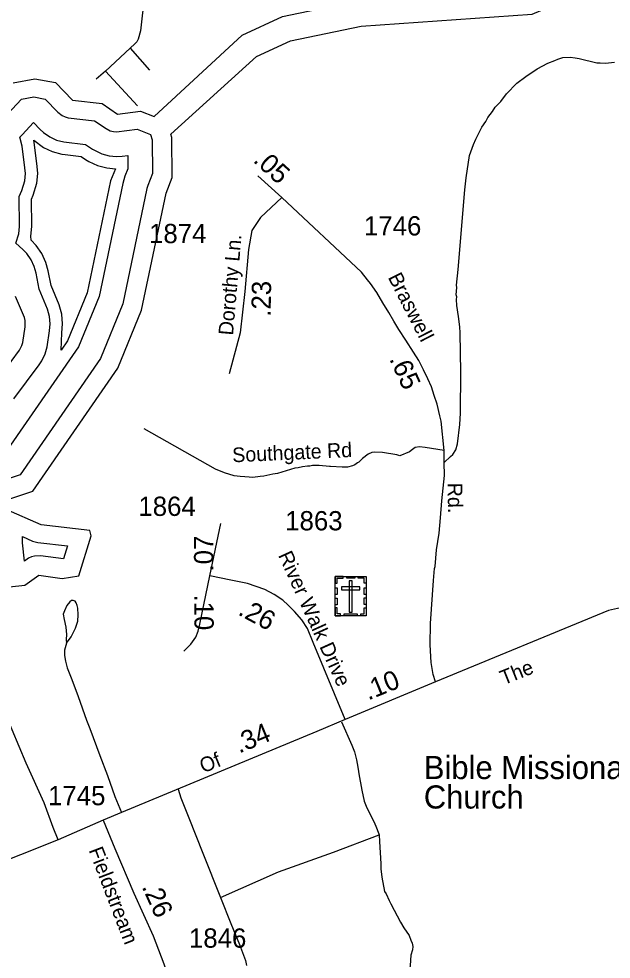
# Model space of a CAD drawing. Extents: x 2220236 to 2384410, y 720751 to 894131.
# Drawn here: x 2329286 to 2333123, y 778623 to 784717 of the extents above; entities that cross this region are included whole.
import ezdxf

# ---------------------------------------------------------------- set-up
doc = ezdxf.new("R2010")
doc.units = 0
doc.layers.add('Default', color=7, linetype='Continuous')

msp = doc.modelspace()

# ---------------------------------------------------------------- linework, layer by layer
at = {"layer": 'Default'}
for p, q in [((2330007.3, 784526.8), (2329846.9, 784377)), ((2330007.3, 784526.8), (2330132.6, 784384.6)), ((2329846.9, 784377), (2329787.7, 784325.1)), ((2329846.9, 784377), (2330054.7, 784153.8)), ((2330990.5, 783558.1), (2330834.7, 783699.1))]:
    msp.add_line(p, q, dxfattribs=at)
for points in [[(2330163, 784084.9), (2330733.1, 784610.8), (2330993, 784731.7), (2331481.8, 784832.8), (2332572.7, 784909.9), (2332829.5, 785019), (2332935.7, 785114), (2333181.2, 785476.6)], [(2330270, 783969.1), (2330825, 784472.6), (2331044.9, 784574.9), (2331504.3, 784670), (2332611.6, 784748.2), (2332918.7, 784878.6), (2333058.6, 785003.8), (2333331.5, 785385.3)], [(2330143.3, 785190.9), (2330086.7, 784756), (2330074.5, 784639.9), (2330058.8, 784585.8), (2330050.1, 784568), (2330037.9, 784554.3), (2330007.3, 784526.8)], [(2332041.4, 781841.1), (2332082.8, 781881), (2332096.7, 781893.2), (2332116.5, 781923.2), (2332128, 781963.5), (2332142.6, 782087.5), (2332147.8, 782161.6), (2332148.9, 782427.5), (2332144.4, 782681.2), (2332141.9, 782721.3), (2332135, 782787), (2332124.3, 782859), (2332121.9, 782898.9), (2332123.8, 782915), (2332119.6, 782928.9), (2332123.1, 782976.8), (2332120.9, 782990.9), (2332131.7, 783093), (2332174.3, 783609.1), (2332183.5, 783687.3), (2332205.8, 783831.5), (2332231.2, 783901.7), (2332246.7, 783937.8), (2332285.8, 784014.2), (2332311.5, 784050.5), (2332323.3, 784076.6), (2332354.8, 784116.9), (2332372.5, 784145), (2332408, 784181.4), (2332445.4, 784231.8), (2332512.8, 784300.6), (2332570.3, 784343.1), (2332643.6, 784393.9), (2332713.1, 784430.6), (2332759.1, 784447.1), (2332776.9, 784455.2), (2332810.7, 784465.6), (2332856.7, 784468.1), (2332888.8, 784464.6), (2332914.8, 784460.8), (2333031, 784432), (2333051, 784432.2), (2333087.1, 784428.7), (2333144.9, 784435.2)], [(2329248.9, 784302.1), (2329390, 784327.5), (2329524.1, 784303.4), (2329633, 784189.7), (2329824.9, 784168), (2329926, 784100), (2330075.1, 784119.1), (2330163, 784084.9)], [(2329179.2, 784064.9), (2329302.5, 784195.9), (2329383.1, 784210.4), (2329457.3, 784197), (2329539.5, 784111.5), (2329566, 784090.6), (2329585, 784081.8), (2329605.3, 784076.4), (2329775.3, 784056.9), (2329852, 784005.3), (2329878.1, 783992), (2329898.4, 783986.6), (2329919.1, 783984.8), (2330053.2, 784001.1), (2330139.1, 783967.6), (2330150.4, 783932.4), (2330152.8, 783715), (2330121.7, 783637), (2330115.5, 783617.1), (2329958.8, 782869.7), (2329813.9, 782514.7), (2329294.3, 781761.7), (2329150.5, 781714.3)], [(2329253.5, 782253.6), (2329417.5, 782473.7), (2329435.5, 782501), (2329456.1, 782545.2), (2329468.8, 782592.3), (2329485.6, 782695.4), (2329489.1, 782740), (2329484.8, 782788.7), (2329472, 782835.8), (2329418.3, 782964.2), (2329397.8, 783069), (2329386.1, 783111.2), (2329365.6, 783155.5), (2329337.5, 783195.5), (2329311.5, 783222.4), (2329267.4, 783262.8), (2329285.9, 783323.3), (2329290, 783371.9), (2329288.5, 783565), (2329305.5, 783604.7), (2329323.8, 783666.2), (2329328.1, 783714.8), (2329325.8, 783750.4), (2329307.8, 783890.8), (2329293, 783950.9), (2329306.8, 783965.9), (2329381, 784045.8), (2329424.1, 784000.8), (2329446, 783980), (2329486, 783952), (2329530.3, 783931.4), (2329577.6, 783918.8), (2329718.5, 783902.3), (2329762.6, 783872.6), (2329823.3, 783841.7), (2329870.7, 783829.1), (2329919.1, 783824.8), (2329954.7, 783827.1), (2329991.6, 783831.8), (2329992.5, 783744.8), (2329973, 783696.5), (2329959, 783650), (2329805.3, 782916.7)], [(2329195, 781595.5), (2329377.1, 781655.5), (2329927.1, 782452.4), (2330081.1, 782829.6), (2330240, 783587.6), (2330280, 783687.7), (2330277.1, 783946.9), (2330270, 783969.1)], [(2329560.2, 782569.7), (2329564.5, 782682.7), (2329569, 782740), (2329563.5, 782802.5), (2329547.3, 782863.2), (2329495.2, 782987.7), (2329476.4, 783084.4), (2329461.4, 783138.6), (2329434.7, 783195.5), (2329398.8, 783246.9), (2329365.6, 783281.5), (2329364.6, 783309.4), (2329370.1, 783371.9), (2329368.5, 783548.9), (2329379.2, 783573.3), (2329402.5, 783652.3), (2329408.1, 783714.8), (2329405, 783760.6), (2329387.2, 783901), (2329382.2, 783930.3), (2329446, 783882.8), (2329502.8, 783856.2), (2329563.5, 783840), (2329585.6, 783836.8), (2329690, 783825.1), (2329717.9, 783806.3), (2329739, 783793), (2329795.8, 783766.5), (2329856.5, 783750.3), (2329912.3, 783745.4), (2329880.7, 783666.4), (2329728.4, 782940.3), (2329601.6, 782629.6), (2329560.2, 782569.7)], [(2330990.5, 783558.1), (2330851.9, 783429.3), (2330795.5, 783344.7), (2330772.6, 783221.2), (2330749.8, 782950.4), (2330720.4, 782682.8), (2330648.6, 782415.3)], [(2331985, 780419.4), (2331970.5, 780467.4), (2331957.2, 780546.3), (2331950, 780660), (2331953.3, 780798.6), (2331971.6, 781076), (2331978.8, 781154.1), (2331982.7, 781168.1), (2331991.5, 781276.3), (2332008.2, 781384.4), (2332017.3, 781482.4), (2332025.9, 781592.2), (2332042.3, 781756.5), (2332041.4, 781841.1), (2332042, 781919.1), (2332021.9, 782110.5), (2332013.3, 782145.1), (2331996, 782218.7), (2331976.5, 782275), (2331959.2, 782331.2), (2331935.4, 782383.2), (2331907.3, 782441.6), (2331877.1, 782502.2), (2331842.5, 782556.3), (2331792.7, 782634.2), (2331747.3, 782704.5), (2331714.9, 782758.6), (2331682.4, 782814.8), (2331643.5, 782875.4), (2331604.6, 782942.5), (2331564.8, 783002.1), (2331544.1, 783024.7), (2331506.6, 783075.6), (2330990.5, 783558.1)], [(2329125.3, 782349.2), (2329289.3, 782569.3), (2329305.7, 782599.9), (2329311.3, 782620.2), (2329327.5, 782720.9), (2329327.3, 782760.9), (2329321.7, 782781.1), (2329264.5, 782917.3)], [(2329805.3, 782916.7), (2329672.4, 782591.3), (2329193, 781896.8)], [(2332042, 781919.1), (2331918.4, 781939.1), (2331880.4, 781942.8), (2331854.4, 781938.5), (2331836.5, 781926.4), (2331816.7, 781910.2), (2331754.9, 781885.4), (2331734.9, 781891.2), (2331642.8, 781906.3), (2331592.9, 781909.6), (2331572.8, 781905.4), (2331549.1, 781895.2), (2331511.4, 781866.9), (2331487.5, 781844.5), (2331479.7, 781840.4), (2331461.8, 781826.2), (2331447.9, 781820.1), (2331414, 781811.7), (2331380, 781811.5), (2331305.9, 781814.7), (2331298, 781816.5), (2331231.9, 781821.8), (2331188, 781821.3), (2331171.9, 781817.2), (2331155.9, 781816.9), (2331124.1, 781812.6), (2331096.1, 781806.3), (2331074.2, 781804.2), (2330962.5, 781770.8), (2330930.7, 781766.5), (2330872.8, 781754), (2330848.8, 781749.8), (2330800.9, 781745.2), (2330778.9, 781746.9), (2330750.5, 781748.1), (2330720.2, 781750.3), (2330681.3, 781754.6), (2330618.6, 781774.1), (2330560.2, 781797.9), (2330097.4, 782059.7)], [(2329226, 781035.5), (2329325, 781046.1), (2329416.1, 781112.2), (2329567, 781088.8), (2329675, 781106.3), (2329755, 781365.7), (2329746, 781401.4), (2329430, 781437.7), (2329204, 781536.8)], [(2330522.3, 781106.7), (2330593.6, 781447)], [(2329322.8, 781202.1), (2329310.3, 781320.9), (2329309.2, 781361.7), (2329374.9, 781332.7), (2329409.3, 781323.4), (2329601, 781301.3), (2329575.4, 781217.8), (2329427.3, 781235.7), (2329388.4, 781235.3), (2329368.1, 781229.8), (2329349, 781221), (2329322.8, 781202.1)], [(2330355.8, 780619.4), (2330400.3, 780663.2), (2330432.1, 780710.5), (2330447.6, 780748.8), (2330458.2, 780793.7), (2330522.3, 781106.7)], [(2331400.6, 780175.5), (2331193.5, 780675.4), (2331155.6, 780765.9), (2331119.7, 780821.4), (2331072.4, 780875.2), (2331031.6, 780916), (2330995.7, 780948.7), (2330940.7, 780985.4), (2330878.7, 781018.8), (2330767.7, 781057.1), (2330658.4, 781080), (2330522.3, 781106.7)], [(2329540.3, 779395.6), (2329509, 779475.4), (2329450.4, 779635.2), (2329333.3, 779893.5), (2329149.7, 780325), (2329043.3, 780591.3), (2329000.7, 780707.1), (2328984.7, 780755), (2328984.7, 780789.7), (2328995.3, 780829.6), (2329022, 780869.6), (2329072.5, 780976.1)], [(2329595, 780671.6), (2329625.2, 780712.4), (2329653.6, 780767.5), (2329667.8, 780813.6), (2329669.6, 780854.5), (2329667.8, 780897.1), (2329664.2, 780914.8), (2329657.1, 780932.6), (2329651.8, 780943.2), (2329637.6, 780946.8), (2329627, 780946.8), (2329616.3, 780937.9), (2329596.8, 780914.8), (2329580.8, 780881.1), (2329573.8, 780858), (2329579.1, 780824.3), (2329589.7, 780774.6), (2329595, 780726.6), (2329593.3, 780694.7), (2329595, 780671.6)], [(2334401.3, 780175.6), (2334301.5, 780217.3), (2334191.6, 780259), (2334010.9, 780345), (2333880.8, 780438.5), (2333782.2, 780532.1), (2333683.7, 780608), (2333496, 780755.2), (2333435.4, 780802), (2333358.3, 780851.3), (2333307, 780886.5), (2333267.3, 780898.1), (2333233.2, 780900.6), (2333204.2, 780903.2), (2333163, 780895.2), (2333106.7, 780882.2), (2331985, 780419.4)], [(2329595, 780671.6), (2329582.6, 780625.4), (2329582.6, 780591.7), (2329587.9, 780554.4), (2329598.6, 780510), (2329628.8, 780435.5), (2329671.3, 780325.4), (2329724.6, 780170.9), (2329745.9, 780117.7), (2329809.7, 779943.5), (2329859.4, 779812.1), (2329907.3, 779677.2), (2329949.9, 779572.4)], [(2331985, 780419.4), (2331400.6, 780175.5)], [(2331400.6, 780175.5), (2331216.8, 780098.7), (2329949.9, 779572.4), (2329831.5, 779523.6)], [(2331375.6, 780160.2), (2331442.6, 780008.8), (2331460.2, 779965.6), (2331474.2, 779915.3), (2331478.4, 779891.4), (2331485, 779853.3), (2331489.2, 779823.5), (2331507.7, 779719), (2331523.7, 779647.3), (2331540.6, 779602.7), (2331585.9, 779515.7), (2331598.3, 779484.3), (2331618.9, 779435.2), (2331621.1, 779429)], [(2330317.1, 779724.8), (2330336.1, 779667.9), (2330387.8, 779538.6), (2330477.3, 779309.4), (2330592.8, 779021.5)], [(2329831.5, 779523.6), (2329540.3, 779395.6), (2329050.9, 779201.8), (2328716.7, 779064), (2328692.8, 779055.7), (2328614.3, 779022.5), (2328493.8, 778971.5), (2328306, 778890.9), (2328185.4, 778832.3), (2328098.2, 778796.3)], [(2329831.5, 779523.6), (2329908.2, 779341), (2330030.6, 779050.7), (2330155.7, 778773.7), (2330224.9, 778592.6), (2330278.1, 778435.5), (2330320.7, 778321), (2330342, 778241.1)], [(2330592.8, 779021.5), (2330968.3, 779188.7), (2331324.8, 779316.3), (2331621.1, 779429)], [(2331621.1, 779429), (2331621.7, 779385.3), (2331631.4, 779241.3), (2331631.8, 779207.3), (2331636.4, 779153.3), (2331655.3, 779061.6), (2331665.6, 779045.6), (2331684, 779002), (2331696.2, 778982.1), (2331757.5, 778862.7), (2331779.8, 778825), (2331813.4, 778776.6), (2331825.7, 778746.7), (2331833.8, 778726.3), (2331837.9, 778704.5), (2331836.5, 778682.7), (2331825.7, 778648.7), (2331820.2, 778580.7), (2331816.1, 778550.8), (2331812.1, 778503.9)], [(2330592.8, 779021.5), (2330659.9, 778854.3), (2330715.1, 778717.3), (2330754.7, 778613.9), (2330759.8, 778581.1)]]:
    msp.add_lwpolyline(points, dxfattribs=at)
for points in [[(2331336, 781103.1), (2331535.1, 781103.1), (2331535.1, 780848.5), (2331336, 780848.5)], [(2331336, 781059.8), (2331347.3, 781059.8), (2331347.3, 781092), (2331387.9, 781092), (2331387.9, 781103.1), (2331336, 781103.1)], [(2331410.1, 781103.1), (2331461.9, 781103.1), (2331461.9, 781091.7), (2331410.1, 781091.7)], [(2331445, 781073.8), (2331426.3, 781073.8), (2331426.3, 780871), (2331445, 780871)], [(2331535.1, 781059.7), (2331523.8, 781059.7), (2331523.8, 781091.9), (2331483.2, 781091.9), (2331483.2, 781103.1), (2331535.1, 781103.1)], [(2331336, 780985.6), (2331336, 781028.9), (2331347.4, 781028.9), (2331347.4, 780985.6)], [(2331376.8, 781035), (2331376.8, 781016.4), (2331494.5, 781016.4), (2331494.5, 781035)], [(2331523.7, 780986.7), (2331523.7, 781030), (2331535.1, 781030), (2331535.1, 780986.7)], [(2331336, 780918.4), (2331336, 780961.7), (2331347.3, 780961.7), (2331347.3, 780918.4)], [(2331523.7, 780920.7), (2331523.7, 780964.1), (2331535.1, 780964.1), (2331535.1, 780920.7)], [(2331369.1, 780848.5), (2331369.1, 780860), (2331347.1, 780860), (2331347.1, 780900.4), (2331335.9, 780900.4), (2331335.9, 780848.5)], [(2331501.9, 780848.5), (2331501.9, 780860), (2331523.9, 780860), (2331523.9, 780900.4), (2331535.1, 780900.4), (2331535.1, 780848.5)], [(2331393.4, 780860), (2331478.3, 780860), (2331478.3, 780848.6), (2331393.4, 780848.6)]]:
    msp.add_lwpolyline(points, close=True, dxfattribs=at)

# ---------------------------------------------------------------- texts
for s, height, rotation, p in [('.05', 125, 317.74014, (2330798.4, 783793.8)), ('Dorothy Ln.', 95, 85.09711, (2330673.1, 782662.9)), ('Braswell', 95, 297.13845, (2331674.9, 783041.9)), ('.23', 125, 89.00789, (2330916.8, 782785.4)), ('.65', 125, 294.60976, (2331683.9, 782513)), ('Southgate Rd', 95, 2.55639, (2330670.4, 781842.6)), ('Rd.', 95, 270.47778, (2332063.9, 781710)), ('.07', 125, 89.85147, (2330545.4, 781134.7)), ('River Walk Drive', 95, 294.34485, (2330963.9, 781241.4)), ('.10', 125, 270.52187, (2330421.6, 780986.1)), ('.26', 125, 331.89732, (2330699.4, 780857.9)), ('The', 95, 21.85115, (2332426.2, 780397.5)), ('.10', 125, 22.17976, (2331549.4, 780298.6)), ('.34', 125, 22.40521, (2330713, 779954.6)), ('Of', 95, 22.4052, (2330480.6, 779826.7)), ('Fieldstream', 95, 290.93707, (2329737, 779329.4)), ('.26', 125, 294.30558, (2330080.5, 779092.1))]:
    msp.add_text(s, height=height, rotation=rotation, dxfattribs=at).set_placement(p)
for s, height, p in [('1874', 125, (2330129.4, 783263.1)), ('1746', 125, (2331521.5, 783312.9)), ('1864', 125, (2330060.3, 781495.4)), ('1863', 125, (2331011.4, 781401.7)), ('Bible Missionary', 150, (2331909.4, 779790)), ('1745', 125, (2329475.1, 779620.3)), ('Church', 150, (2331909.4, 779599)), ('1846', 125, (2330387.9, 778697.2))]:
    msp.add_text(s, height=height, dxfattribs=at).set_placement(p)

doc.saveas('drawing.dxf')
